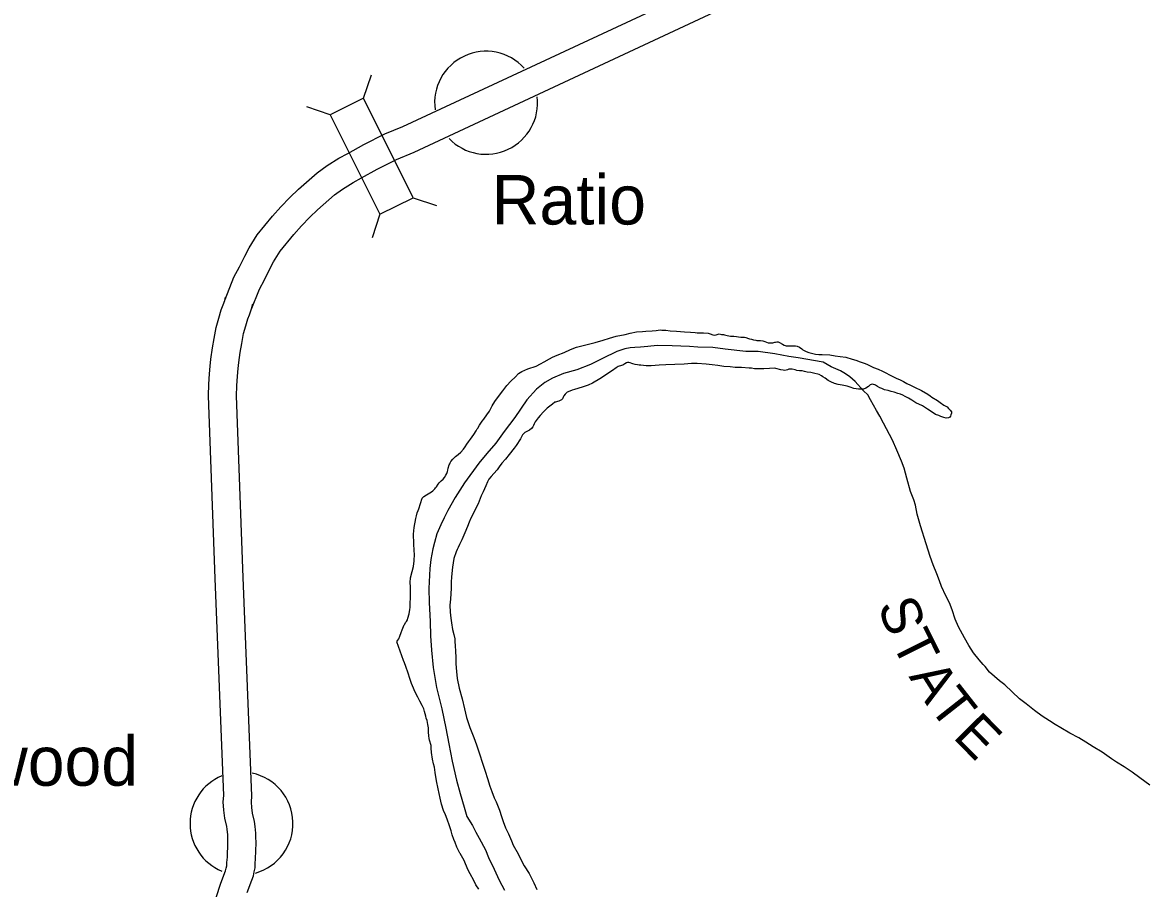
# Model space of a CAD drawing. Extents: x -939622 to -934222, y 1383701 to 1385301.
# Drawn here: x -935854.11 to -935818.1, y 1383878.47 to 1383906.21 of the extents above; entities that cross this region are included whole.
import ezdxf

# ---------------------------------------------------------------- set-up
doc = ezdxf.new("R2010")
doc.units = 0
for name, color, linetype in [('Level 10', 7, 'Continuous'), ('Level 20', 7, 'Continuous'), ('Level 24', 7, 'Continuous'), ('Level 3', 7, 'Continuous'), ('Level 9', 7, 'Continuous')]:
    doc.layers.add(name, color=color, linetype=linetype)

msp = doc.modelspace()

# ---------------------------------------------------------------- linework, layer by layer
at = {"layer": 'Level 10'}
for points in [[(-935847.621, 1383897.338), (-935847.338, 1383898.054), (-935847.157, 1383898.386), (-935846.987, 1383898.733), (-935846.848, 1383899), (-935846.589, 1383899.411), (-935846.102, 1383900.009), (-935845.831, 1383900.31), (-935845.543, 1383900.612), (-935845.266, 1383900.875), (-935844.673, 1383901.403), (-935844.354, 1383901.628), (-935843.973, 1383901.863), (-935843.686, 1383902.021), (-935843.173, 1383902.309), (-935842.501, 1383902.645), (-935841.926, 1383902.886), (-935832.166, 1383907.431)], [(-935846.784, 1383897.007), (-935846.521, 1383897.672), (-935846.358, 1383897.973), (-935846.185, 1383898.326), (-935846.066, 1383898.552), (-935845.857, 1383898.885), (-935845.418, 1383899.423), (-935845.17, 1383899.699), (-935844.907, 1383899.975), (-935844.657, 1383900.212), (-935844.112, 1383900.697), (-935843.858, 1383900.877), (-935843.519, 1383901.086), (-935843.249, 1383901.235), (-935842.751, 1383901.513), (-935842.125, 1383901.827), (-935841.562, 1383902.063), (-935831.787, 1383906.615)], [(-935849.432, 1383873.483), (-935847.76, 1383878.642), (-935847.611, 1383879.038), (-935847.582, 1383879.123), (-935847.566, 1383879.194), (-935847.561, 1383879.22), (-935847.561, 1383879.307), (-935847.545, 1383879.477), (-935847.528, 1383879.933), (-935847.534, 1383880.1), (-935847.537, 1383880.189), (-935847.552, 1383880.373), (-935847.561, 1383880.457), (-935847.627, 1383880.721), (-935847.661, 1383880.977), (-935847.678, 1383881.244), (-935847.664, 1383881.454), (-935847.942, 1383888.399), (-935848.154, 1383894.258), (-935848.142, 1383894.627), (-935848.116, 1383894.956), (-935848.098, 1383895.201), (-935848.077, 1383895.429), (-935848.026, 1383895.795), (-935847.967, 1383896.096), (-935847.907, 1383896.441), (-935847.826, 1383896.741), (-935847.747, 1383897.006), (-935847.684, 1383897.17), (-935847.633, 1383897.306), (-935847.605, 1383897.418)], [(-935846.91, 1383878.345), (-935846.763, 1383878.736), (-935846.716, 1383878.877), (-935846.685, 1383879.006), (-935846.66, 1383879.138), (-935846.661, 1383879.268), (-935846.647, 1383879.417), (-935846.627, 1383879.932), (-935846.635, 1383880.132), (-935846.638, 1383880.242), (-935846.656, 1383880.459), (-935846.674, 1383880.616), (-935846.741, 1383880.889), (-935846.765, 1383881.065), (-935846.776, 1383881.242), (-935846.763, 1383881.442), (-935847.043, 1383888.434), (-935847.254, 1383894.259), (-935847.243, 1383894.577), (-935847.219, 1383894.888), (-935847.201, 1383895.126), (-935847.183, 1383895.327), (-935847.139, 1383895.645), (-935847.082, 1383895.932), (-935847.027, 1383896.247), (-935846.96, 1383896.495), (-935846.894, 1383896.716), (-935846.842, 1383896.851), (-935846.772, 1383897.039), (-935846.732, 1383897.2)]]:
    msp.add_lwpolyline(points, dxfattribs=at)
at = {"layer": 'Level 20'}
for p, q in [((-935843.187, 1383903.79), (-935842.935, 1383904.541)), ((-935844.25, 1383903.26), (-935845.001, 1383903.511)), ((-935841.596, 1383900.601), (-935840.845, 1383900.349)), ((-935842.659, 1383900.071), (-935842.911, 1383899.319))]:
    msp.add_line(p, q, dxfattribs=at)
msp.add_lwpolyline([(-935841.596, 1383900.601), (-935843.187, 1383903.79), (-935844.25, 1383903.26), (-935842.659, 1383900.071)], close=True, dxfattribs=at)
at = {"layer": 'Level 24'}
for centre, start, end in [((-935839.258, 1383903.642), 42.1845, 187.7651), ((-935839.258, 1383903.642), 224.0906, 6.789), ((-935847.095, 1383880.554), 285.9454, 77.9052), ((-935847.095, 1383880.554), 112.5206, 247.4794)]:
    msp.add_arc(centre, 1.65, start, end, dxfattribs=at)
at = {"layer": 'Level 3'}
for points in [[(-935817.985, 1383881.779), (-935818.316, 1383882.013), (-935818.553, 1383882.199), (-935818.815, 1383882.367), (-935819.055, 1383882.523), (-935819.217, 1383882.628), (-935819.521, 1383882.835), (-935819.809, 1383883.015), (-935820.044, 1383883.156), (-935820.263, 1383883.296), (-935820.557, 1383883.449), (-935820.84, 1383883.62), (-935821.026, 1383883.722), (-935821.206, 1383883.839), (-935821.438, 1383883.995), (-935821.684, 1383884.169), (-935821.955, 1383884.391), (-935822.162, 1383884.547), (-935822.634, 1383884.991), (-935822.806, 1383885.126), (-935823.124, 1383885.399), (-935823.266, 1383885.579), (-935823.329, 1383885.648), (-935823.456, 1383885.792), (-935823.636, 1383886.018), (-935823.787, 1383886.258), (-935823.925, 1383886.498), (-935824.118, 1383886.853), (-935824.224, 1383887.096), (-935824.324, 1383887.397), (-935824.414, 1383887.619), (-935824.532, 1383887.847), (-935824.662, 1383888.148), (-935824.734, 1383888.331), (-935824.819, 1383888.547), (-935824.937, 1383888.845), (-935825.034, 1383889.109), (-935825.158, 1383889.512), (-935825.339, 1383890.092), (-935825.442, 1383890.468), (-935825.503, 1383890.75), (-935825.557, 1383890.922), (-935825.657, 1383891.186), (-935825.775, 1383891.613), (-935825.863, 1383891.941), (-935825.945, 1383892.157), (-935826.093, 1383892.518), (-935826.232, 1383892.83), (-935826.524, 1383893.374), (-935826.642, 1383893.608), (-935826.747, 1383893.785), (-935826.847, 1383893.957), (-935826.937, 1383894.122), (-935827.031, 1383894.287), (-935827.166, 1383894.419), (-935827.428, 1383894.71), (-935827.602, 1383894.86), (-935827.737, 1383894.959), (-935827.903, 1383895.055), (-935828.197, 1383895.187), (-935828.461, 1383895.337), (-935829.263, 1383895.474), (-935829.554, 1383895.515), (-935830.01, 1383895.601), (-935830.544, 1383895.676), (-935830.934, 1383895.678), (-935831.6, 1383895.749), (-935831.996, 1383895.799), (-935832.473, 1383895.81), (-935832.74, 1383895.831), (-935833.301, 1383895.854), (-935833.775, 1383895.862), (-935834.072, 1383895.834), (-935834.312, 1383895.816), (-935834.489, 1383895.803), (-935834.645, 1383895.788), (-935834.81, 1383895.758), (-935835.07, 1383895.673), (-935835.532, 1383895.45), (-935835.909, 1383895.259)], [(-935835.909, 1383895.259), (-935836.353, 1383895.09), (-935836.775, 1383894.969), (-935837.126, 1383894.818), (-935837.38, 1383894.685), (-935837.647, 1383894.465), (-935837.955, 1383894.128), (-935838.34, 1383893.556), (-935838.681, 1383893.107), (-935838.95, 1383892.743), (-935839.234, 1383892.402), (-935839.488, 1383892.092), (-935839.954, 1383891.463), (-935840.253, 1383890.993), (-935840.483, 1383890.577), (-935840.605, 1383890.346), (-935840.712, 1383890.12), (-935840.834, 1383889.834), (-935840.906, 1383889.56), (-935840.962, 1383889.353), (-935841.033, 1383889.01), (-935841.062, 1383888.727), (-935841.071, 1383888.51), (-935841.088, 1383888.08), (-935841.077, 1383887.632), (-935841.055, 1383887.028), (-935841.035, 1383886.571), (-935841.01, 1383886.102), (-935840.955, 1383885.551), (-935840.848, 1383884.908), (-935840.678, 1383884.226), (-935840.55, 1383883.603), (-935840.45, 1383883.104), (-935840.346, 1383882.548), (-935840.201, 1383881.938), (-935840.088, 1383881.514), (-935839.961, 1383881.072), (-935839.87, 1383880.778), (-935839.696, 1383880.493), (-935839.587, 1383880.276), (-935839.485, 1383880.087), (-935839.277, 1383879.708), (-935839.18, 1383879.465), (-935839.002, 1383879.096), (-935838.836, 1383878.744), (-935838.664, 1383878.42)]]:
    msp.add_lwpolyline(points, dxfattribs=at)
at = {"layer": 'Level 9'}
for points in [[(-935841.511, 1383890.32), (-935841.493, 1383890.413), (-935841.463, 1383890.506), (-935841.439, 1383890.579), (-935841.416, 1383890.639), (-935841.302, 1383890.976), (-935841.249, 1383891.03), (-935841.168, 1383891.078), (-935841.006, 1383891.175), (-935840.964, 1383891.214), (-935840.904, 1383891.277), (-935840.877, 1383891.307), (-935840.851, 1383891.341), (-935840.794, 1383891.422), (-935840.761, 1383891.464), (-935840.698, 1383891.53), (-935840.638, 1383891.582), (-935840.59, 1383891.639), (-935840.543, 1383891.714), (-935840.516, 1383891.765), (-935840.498, 1383891.828), (-935840.483, 1383891.871), (-935840.468, 1383891.937), (-935840.439, 1383892.042), (-935840.421, 1383892.081), (-935840.406, 1383892.108), (-935840.385, 1383892.147), (-935840.322, 1383892.229), (-935840.235, 1383892.31), (-935840.149, 1383892.37), (-935840.062, 1383892.452), (-935839.984, 1383892.542), (-935839.924, 1383892.623), (-935839.87, 1383892.702), (-935839.817, 1383892.777), (-935839.757, 1383892.861), (-935839.652, 1383893.015), (-935839.578, 1383893.135), (-935839.554, 1383893.174), (-935839.542, 1383893.198), (-935839.527, 1383893.217), (-935839.473, 1383893.31), (-935839.384, 1383893.439), (-935839.333, 1383893.509), (-935839.237, 1383893.641), (-935839.154, 1383893.759), (-935839.058, 1383893.933), (-935838.977, 1383894.069), (-935838.864, 1383894.237), (-935838.726, 1383894.409), (-935838.589, 1383894.584), (-935838.469, 1383894.719), (-935838.32, 1383894.867), (-935838.215, 1383894.969), (-935838.116, 1383895.036), (-935837.921, 1383895.117), (-935837.658, 1383895.205), (-935837.517, 1383895.283), (-935837.394, 1383895.347), (-935837.226, 1383895.443), (-935837.131, 1383895.492), (-935836.984, 1383895.555), (-935836.759, 1383895.643), (-935836.558, 1383895.742), (-935836.361, 1383895.809), (-935836.151, 1383895.866), (-935835.98, 1383895.912), (-935835.767, 1383895.96), (-935835.506, 1383896.036), (-935835.3, 1383896.103), (-935835.09, 1383896.163), (-935834.799, 1383896.221), (-935834.643, 1383896.26), (-935834.442, 1383896.3), (-935834.25, 1383896.318), (-935834.142, 1383896.324), (-935833.935, 1383896.34), (-935833.809, 1383896.349), (-935833.68, 1383896.364), (-935833.623, 1383896.361), (-935833.5, 1383896.353), (-935833.356, 1383896.341), (-935833.155, 1383896.323), (-935832.9, 1383896.306), (-935832.711, 1383896.291), (-935832.555, 1383896.282), (-935832.498, 1383896.273), (-935832.372, 1383896.268), (-935832.291, 1383896.268), (-935832.141, 1383896.259), (-935832.078, 1383896.235), (-935831.991, 1383896.205), (-935831.943, 1383896.199), (-935831.886, 1383896.211), (-935831.826, 1383896.23), (-935831.787, 1383896.239), (-935831.718, 1383896.224), (-935831.655, 1383896.215), (-935831.616, 1383896.206), (-935831.538, 1383896.182), (-935831.424, 1383896.164)], [(-935831.424, 1383896.164), (-935831.316, 1383896.164), (-935831.235, 1383896.152), (-935831.169, 1383896.141), (-935831.091, 1383896.138), (-935831.058, 1383896.138), (-935831.013, 1383896.132), (-935830.98, 1383896.129), (-935830.938, 1383896.12), (-935830.848, 1383896.096), (-935830.815, 1383896.081), (-935830.755, 1383896.066), (-935830.686, 1383896.048), (-935830.611, 1383896.036), (-935830.581, 1383896.03), (-935830.467, 1383896.022), (-935830.392, 1383896.016), (-935830.356, 1383896.01), (-935830.329, 1383895.998), (-935830.269, 1383895.971), (-935830.221, 1383895.95), (-935830.167, 1383895.947), (-935830.104, 1383895.953), (-935830.074, 1383895.956), (-935830.011, 1383895.971), (-935829.984, 1383895.977), (-935829.942, 1383895.984), (-935829.9, 1383895.981), (-935829.855, 1383895.96), (-935829.762, 1383895.906), (-935829.708, 1383895.879), (-935829.645, 1383895.858), (-935829.603, 1383895.852), (-935829.531, 1383895.852), (-935829.468, 1383895.855), (-935829.429, 1383895.861), (-935829.384, 1383895.861), (-935829.348, 1383895.861), (-935829.288, 1383895.843), (-935829.219, 1383895.808), (-935829.143, 1383895.76), (-935829.107, 1383895.73), (-935829.047, 1383895.691), (-935828.999, 1383895.67), (-935828.915, 1383895.64), (-935828.708, 1383895.589), (-935828.594, 1383895.58), (-935828.486, 1383895.577), (-935828.24, 1383895.566), (-935828.069, 1383895.539), (-935827.913, 1383895.518), (-935827.727, 1383895.489), (-935827.523, 1383895.432), (-935827.415, 1383895.393), (-935827.267, 1383895.342), (-935827.114, 1383895.285), (-935827.033, 1383895.255), (-935826.847, 1383895.165), (-935826.7, 1383895.106), (-935826.559, 1383895.046), (-935826.448, 1383894.986), (-935826.33, 1383894.929), (-935826.12, 1383894.821), (-935825.994, 1383894.767), (-935825.883, 1383894.71), (-935825.778, 1383894.653), (-935825.661, 1383894.599), (-935825.595, 1383894.569), (-935825.465, 1383894.504), (-935825.375, 1383894.462), (-935825.303, 1383894.42), (-935825.108, 1383894.312), (-935825.03, 1383894.258), (-935824.976, 1383894.207), (-935824.795, 1383894.102), (-935824.708, 1383894.036), (-935824.591, 1383893.958), (-935824.48, 1383893.898), (-935824.438, 1383893.853), (-935824.387, 1383893.79), (-935824.347, 1383893.739), (-935824.347, 1383893.694), (-935824.362, 1383893.643), (-935824.38, 1383893.603), (-935824.401, 1383893.573), (-935824.443, 1383893.552), (-935824.518, 1383893.543), (-935824.59, 1383893.555), (-935824.686, 1383893.597), (-935824.749, 1383893.621), (-935824.857, 1383893.66), (-935824.968, 1383893.732), (-935825.119, 1383893.828), (-935825.275, 1383893.933), (-935825.485, 1383894.034), (-935825.617, 1383894.112), (-935825.725, 1383894.175), (-935825.834, 1383894.238), (-935825.903, 1383894.271), (-935825.978, 1383894.304), (-935826.065, 1383894.331)], [(-935826.065, 1383894.331), (-935826.182, 1383894.367), (-935826.278, 1383894.391), (-935826.374, 1383894.421), (-935826.491, 1383894.45), (-935826.578, 1383894.489), (-935826.638, 1383894.513), (-935826.716, 1383894.549), (-935826.779, 1383894.591), (-935826.806, 1383894.603), (-935826.846, 1383894.621), (-935826.873, 1383894.627), (-935826.918, 1383894.621), (-935826.953, 1383894.606), (-935827.01, 1383894.552), (-935827.088, 1383894.5), (-935827.169, 1383894.464), (-935827.328, 1383894.464), (-935827.475, 1383894.488), (-935827.589, 1383894.527), (-935827.691, 1383894.565), (-935827.847, 1383894.592), (-935827.973, 1383894.619), (-935828.093, 1383894.646), (-935828.217, 1383894.7), (-935828.295, 1383894.742), (-935828.397, 1383894.817), (-935828.463, 1383894.868), (-935828.514, 1383894.898), (-935828.583, 1383894.934), (-935828.625, 1383894.946), (-935828.727, 1383894.972), (-935828.856, 1383894.999), (-935828.973, 1383895.014), (-935829.051, 1383895.032), (-935829.126, 1383895.05), (-935829.219, 1383895.059), (-935829.3, 1383895.071), (-935829.354, 1383895.082), (-935829.451, 1383895.109), (-935829.475, 1383895.109), (-935829.553, 1383895.109), (-935829.603, 1383895.085), (-935829.681, 1383895.07), (-935829.741, 1383895.079), (-935829.813, 1383895.091), (-935829.973, 1383895.135), (-935830.027, 1383895.141), (-935830.174, 1383895.135), (-935830.362, 1383895.12), (-935830.581, 1383895.119), (-935830.656, 1383895.119), (-935830.752, 1383895.14), (-935830.83, 1383895.143), (-935831.079, 1383895.16), (-935831.28, 1383895.16), (-935831.433, 1383895.178), (-935831.64, 1383895.198), (-935831.833, 1383895.225), (-935832.019, 1383895.252), (-935832.208, 1383895.269), (-935832.49, 1383895.287), (-935832.673, 1383895.29), (-935832.913, 1383895.268), (-935833.215, 1383895.253), (-935833.5, 1383895.249), (-935833.707, 1383895.24), (-935833.965, 1383895.218), (-935834.133, 1383895.218), (-935834.214, 1383895.224), (-935834.298, 1383895.232), (-935834.349, 1383895.238), (-935834.403, 1383895.244), (-935834.481, 1383895.262), (-935834.556, 1383895.28), (-935834.592, 1383895.295), (-935834.64, 1383895.31), (-935834.688, 1383895.319), (-935834.709, 1383895.322), (-935834.73, 1383895.322), (-935834.757, 1383895.31), (-935834.814, 1383895.283), (-935834.88, 1383895.24), (-935834.922, 1383895.231), (-935835.027, 1383895.195), (-935835.093, 1383895.153), (-935835.207, 1383895.071), (-935835.392, 1383894.948), (-935835.461, 1383894.893), (-935835.617, 1383894.797), (-935835.853, 1383894.664), (-935835.991, 1383894.601), (-935836.147, 1383894.546), (-935836.318, 1383894.489), (-935836.429, 1383894.452), (-935836.501, 1383894.437), (-935836.579, 1383894.407), (-935836.657, 1383894.374), (-935836.692, 1383894.344), (-935836.728, 1383894.308), (-935836.767, 1383894.259)], [(-935836.767, 1383894.259), (-935836.791, 1383894.208), (-935836.812, 1383894.16), (-935836.839, 1383894.121), (-935836.923, 1383894.088), (-935836.968, 1383894.073), (-935837.034, 1383894.054), (-935837.058, 1383894.048), (-935837.129, 1383893.991), (-935837.297, 1383893.855), (-935837.417, 1383893.741), (-935837.53, 1383893.629), (-935837.587, 1383893.551), (-935837.62, 1383893.509), (-935837.683, 1383893.422), (-935837.719, 1383893.355), (-935837.742, 1383893.304), (-935837.76, 1383893.256), (-935837.799, 1383893.205), (-935837.868, 1383893.151), (-935838.015, 1383893.081), (-935838.075, 1383893.03), (-935838.09, 1383893), (-935838.155, 1383892.879), (-935838.299, 1383892.663), (-935838.361, 1383892.575), (-935838.517, 1383892.373), (-935838.639, 1383892.226), (-935838.75, 1383892.093), (-935838.834, 1383891.979), (-935838.905, 1383891.886), (-935839.007, 1383891.762), (-935839.097, 1383891.666), (-935839.165, 1383891.587), (-935839.213, 1383891.497), (-935839.264, 1383891.371), (-935839.347, 1383891.175), (-935839.413, 1383891.052), (-935839.452, 1383890.961), (-935839.511, 1383890.793), (-935839.75, 1383890.332), (-935839.798, 1383890.203), (-935839.851, 1383890.067), (-935839.935, 1383889.866), (-935840.033, 1383889.643), (-935840.111, 1383889.495), (-935840.158, 1383889.396), (-935840.185, 1383889.33), (-935840.218, 1383889.252), (-935840.289, 1383889.038), (-935840.33, 1383888.761), (-935840.363, 1383888.451), (-935840.374, 1383888.289), (-935840.377, 1383888.094), (-935840.403, 1383887.745), (-935840.417, 1383887.543), (-935840.407, 1383887.321), (-935840.386, 1383887.134), (-935840.371, 1383886.978), (-935840.334, 1383886.764), (-935840.295, 1383886.611), (-935840.264, 1383886.473), (-935840.255, 1383886.38), (-935840.249, 1383886.241), (-935840.236, 1383886.073), (-935840.232, 1383885.872), (-935840.223, 1383885.667), (-935840.204, 1383885.426), (-935840.18, 1383885.201), (-935840.116, 1383884.891), (-935840.025, 1383884.552), (-935839.952, 1383884.224), (-935839.888, 1383883.951), (-935839.776, 1383883.629), (-935839.719, 1383883.47), (-935839.652, 1383883.307), (-935839.562, 1383883.073), (-935839.465, 1383882.785), (-935839.368, 1383882.487), (-935839.284, 1383882.232), (-935839.211, 1383881.994), (-935839.138, 1383881.751), (-935839.072, 1383881.576), (-935838.999, 1383881.378), (-935838.939, 1383881.243), (-935838.833, 1383880.981), (-935838.761, 1383880.777), (-935838.712, 1383880.615), (-935838.634, 1383880.41), (-935838.543, 1383880.221), (-935838.449, 1383880.002), (-935838.389, 1383879.855), (-935838.235, 1383879.587), (-935838.127, 1383879.353), (-935838.039, 1383879.2), (-935837.883, 1383878.95), (-935837.729, 1383878.65), (-935837.635, 1383878.443)], [(-935839.492, 1383878.448), (-935839.582, 1383878.592), (-935839.655, 1383878.724), (-935839.763, 1383878.938), (-935839.839, 1383879.076), (-935839.963, 1383879.373), (-935840.089, 1383879.593), (-935840.095, 1383879.605), (-935840.195, 1383879.8), (-935840.252, 1383879.944), (-935840.291, 1383880.046), (-935840.346, 1383880.194), (-935840.382, 1383880.314), (-935840.431, 1383880.479), (-935840.503, 1383880.693), (-935840.563, 1383880.828), (-935840.627, 1383880.972), (-935840.684, 1383881.176), (-935840.727, 1383881.363), (-935840.797, 1383881.663), (-935840.842, 1383881.925), (-935840.885, 1383882.186), (-935840.916, 1383882.355), (-935840.946, 1383882.463), (-935840.979, 1383882.61), (-935841.004, 1383882.833), (-935841.016, 1383882.971), (-935841.023, 1383883.049), (-935841.074, 1383883.227), (-935841.08, 1383883.272), (-935841.089, 1383883.359), (-935841.099, 1383883.482), (-935841.108, 1383883.623), (-935841.12, 1383883.729), (-935841.151, 1383883.852), (-935841.175, 1383883.927), (-935841.19, 1383883.99), (-935841.208, 1383884.068), (-935841.227, 1383884.14), (-935841.254, 1383884.228), (-935841.302, 1383884.336), (-935841.377, 1383884.474), (-935841.444, 1383884.603), (-935841.54, 1383884.786), (-935841.586, 1383884.889), (-935841.646, 1383885.039), (-935841.703, 1383885.204), (-935841.758, 1383885.375), (-935841.833, 1383885.583), (-935841.873, 1383885.706), (-935841.9, 1383885.778), (-935842.118, 1383886.37), (-935842.106, 1383886.4), (-935842.088, 1383886.427), (-935842.058, 1383886.469), (-935842.022, 1383886.56), (-935841.983, 1383886.668), (-935841.951, 1383886.761), (-935841.879, 1383886.921), (-935841.876, 1383886.933), (-935841.825, 1383887.002), (-935841.807, 1383887.026), (-935841.775, 1383887.083), (-935841.763, 1383887.129), (-935841.721, 1383887.27), (-935841.698, 1383887.414), (-935841.695, 1383887.478), (-935841.689, 1383887.583), (-935841.684, 1383887.811), (-935841.681, 1383887.899), (-935841.685, 1383888.133), (-935841.691, 1383888.278), (-935841.676, 1383888.419), (-935841.623, 1383888.63), (-935841.587, 1383888.792), (-935841.561, 1383888.972), (-935841.555, 1383889.183), (-935841.562, 1383889.291), (-935841.577, 1383889.523), (-935841.581, 1383889.82), (-935841.561, 1383890.04), (-935841.511, 1383890.32)]]:
    msp.add_lwpolyline(points, dxfattribs=at)

# ---------------------------------------------------------------- texts
at = {"layer": 'Level 24'}
for s, p in [('Ratio', (-935839.079, 1383899.743)), ('Mellwood', (-935859.357, 1383881.764))]:
    msp.add_text(s, height=1.584, dxfattribs=at).set_placement(p)
at = {"layer": 'Level 3'}
for s, rotation, p in [('S', 290.2475, (-935826.722, 1383887.54)), ('T', 296.4017, (-935826.286, 1383886.373)), ('A', 302.3906, (-935825.728, 1383885.26)), ('T', 308.1762, (-935825.107, 1383884.291)), ('E', 314.5657, (-935824.333, 1383883.315))]:
    msp.add_text(s, height=1.267, rotation=rotation, dxfattribs=at).set_placement(p)

doc.saveas('drawing.dxf')
